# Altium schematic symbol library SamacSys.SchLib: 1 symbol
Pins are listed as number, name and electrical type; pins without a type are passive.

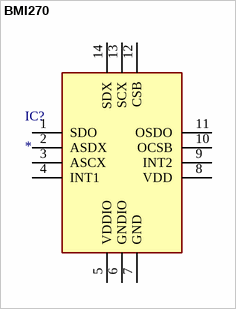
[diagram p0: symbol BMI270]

## BMI270
designator IC?
Integrated Circuit; Manufacturer_Name: BOSCH; Manufacturer_Part_Number: BMI270; Description: IMUs - Inertial Measurement Units Smart Ultra-Low Power Inertial Measurement Unit (IMU) for Wearable Applications
footprint BMI270
pins: 1 SDO, 2 ASDX, 3 ASCX, 4 INT1, 5 VDDIO, 6 GNDIO, 7 GND, 8 VDD, 9 INT2, 10 OCSB, 11 OSDO, 12 CSB, 13 SCX, 14 SDX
